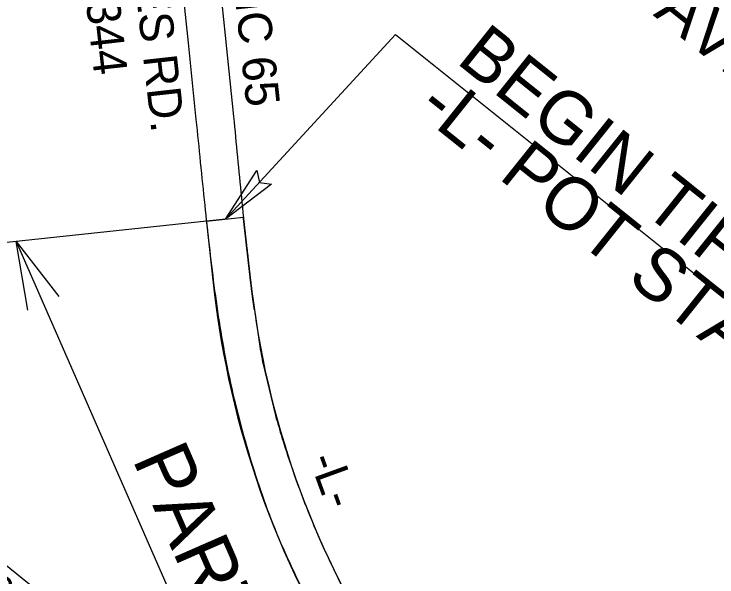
# Model space of a CAD drawing. Extents: x 1730256 to 1738218, y 910410 to 917906.
# Drawn here: x 1735145.7 to 1735520.4, y 915705.2 to 916005.2 of the extents above; entities that cross this region are included whole.
import ezdxf

# ---------------------------------------------------------------- set-up
doc = ezdxf.new("R2010")
doc.units = 0
for name, color, linetype in [('Old_Level_23', 7, 'Continuous'), ('Old_Level_3', 7, 'Continuous'), ('Prop DSN Text', 7, 'Continuous'), ('Prop EOT', 7, 'Continuous'), ('Prop Horizontal Alignment Direction Label', 7, 'Continuous'), ('Prop Shade Light', 7, 'Continuous'), ('Sheet Data Field CELL', 7, 'Continuous')]:
    doc.layers.add(name, color=color, linetype=linetype)

msp = doc.modelspace()

# ---------------------------------------------------------------- linework, layer by layer
at = {"layer": 'Old_Level_23'}
for p, q in [((1735258.41, 915895.78), (1735097.13, 915878.75)), ((1735146.86, 915884), (1735391.91, 915324.39))]:
    msp.add_line(p, q, dxfattribs=at)
at = {"layer": 'Old_Level_3'}
for p, q in [((1735272.09, 915859.75), (1735276.11, 915831.82)), ((1735278.29, 915819.37), (1735285.1, 915791.17))]:
    msp.add_line(p, q, dxfattribs=at)
for points in [[(1735247.81, 916093.77), (1735249.46, 916078.82), (1735253.85, 916036.52), (1735258.32, 915993.7), (1735262.74, 915950.51)], [(1735227.91, 916091.68), (1735229.71, 916074.46), (1735234.16, 916032), (1735238.59, 915989.91), (1735242.69, 915948.94)]]:
    msp.add_lwpolyline(points, dxfattribs=at)
for points in [[(1735262.74, 915950.51), (1735266.87, 915907.53), (1735271.65, 915863.46), (1735272.09, 915859.75)], [(1735242.69, 915948.94), (1735247.35, 915903.38), (1735252.28, 915860.46), (1735259.33, 915816.86), (1735270.45, 915772.23), (1735284.64, 915731.05), (1735303.25, 915691.23), (1735326.98, 915650.38), (1735351.32, 915614.71)], [(1735276.11, 915831.82), (1735277.9, 915821.51), (1735278.29, 915819.37)], [(1735285.1, 915791.17), (1735288.52, 915779.54), (1735302.56, 915739.9), (1735320.07, 915701.16), (1735342.82, 915660.37), (1735365.49, 915624.75)]]:
    msp.add_spline(points, degree=3, dxfattribs=at)
at = {"layer": 'Prop DSN Text'}
for p, q in [((1735258.41, 915895.78), (1735349.06, 915994.36)), ((1735349.06, 915994.36), (1735699.95, 915713.54)), ((1734996.62, 915827.33), (1735214.11, 915653.28))]:
    msp.add_line(p, q, dxfattribs=at)
msp.add_lwpolyline([(1735282.92, 915914.55), (1735258.41, 915895.78), (1735275.07, 915921.78), (1735276.47, 915915.42)], close=True, dxfattribs=at)
msp.add_lwpolyline([(1735153.04, 915847.42), (1735146.86, 915884), (1735169.53, 915854.63)], dxfattribs=at)
at = {"layer": 'Prop EOT'}
msp.add_line((1735267.95, 915896.78), (1735248.26, 915894.71), dxfattribs=at)
for radius in [485, 465]:
    msp.add_arc((1735734.25, 915912.74), radius, 188.0669, 214.0997, dxfattribs=at)
for points in [[(1735248.26, 915894.71), (1735248.34, 915894.03), (1735248.41, 915893.36), (1735248.48, 915892.69), (1735248.56, 915892.02), (1735248.63, 915891.35), (1735248.7, 915890.68), (1735248.78, 915890), (1735248.85, 915889.33), (1735248.93, 915888.66), (1735249, 915887.99), (1735249.07, 915887.32), (1735249.15, 915886.65), (1735249.22, 915885.97), (1735249.29, 915885.3), (1735249.37, 915884.63), (1735249.44, 915883.96), (1735249.51, 915883.29), (1735249.59, 915882.62), (1735249.66, 915881.94), (1735249.74, 915881.27), (1735249.81, 915880.6), (1735249.88, 915879.93), (1735249.96, 915879.26), (1735250.03, 915878.59), (1735250.1, 915877.91), (1735250.18, 915877.24), (1735250.25, 915876.57), (1735250.32, 915875.9), (1735250.4, 915875.23), (1735250.47, 915874.56), (1735250.54, 915873.88), (1735250.62, 915873.21), (1735250.69, 915872.54), (1735250.77, 915871.87), (1735250.84, 915871.2), (1735250.91, 915870.53), (1735250.99, 915869.85), (1735251.06, 915869.18), (1735251.13, 915868.51), (1735251.21, 915867.84), (1735251.28, 915867.17), (1735251.35, 915866.5), (1735251.43, 915865.82), (1735251.5, 915865.15), (1735251.58, 915864.48), (1735251.65, 915863.81), (1735251.72, 915863.14), (1735251.8, 915862.47), (1735251.87, 915861.79), (1735251.95, 915861.11), (1735252.02, 915860.42), (1735252.1, 915859.74), (1735252.18, 915859.05), (1735252.26, 915858.37), (1735252.34, 915857.68), (1735252.42, 915856.99), (1735252.5, 915856.31), (1735252.59, 915855.62), (1735252.67, 915854.94), (1735252.76, 915854.26), (1735252.84, 915853.57), (1735252.93, 915852.89), (1735253.02, 915852.2), (1735253.11, 915851.52), (1735253.2, 915850.83), (1735253.29, 915850.15), (1735253.38, 915849.47), (1735253.47, 915848.78), (1735253.57, 915848.1), (1735253.66, 915847.42), (1735253.76, 915846.73), (1735253.86, 915846.05), (1735254.05, 915844.68)], [(1735267.95, 915896.78), (1735268.02, 915896.11), (1735268.1, 915895.44), (1735268.17, 915894.77), (1735268.25, 915894.1), (1735268.33, 915893.43), (1735268.4, 915892.75), (1735268.48, 915892.08), (1735268.56, 915891.41), (1735268.63, 915890.74), (1735268.71, 915890.07), (1735268.79, 915889.4), (1735268.86, 915888.73), (1735268.94, 915888.06), (1735269.01, 915887.38), (1735269.09, 915886.71), (1735269.17, 915886.04), (1735269.24, 915885.37), (1735269.32, 915884.7), (1735269.4, 915884.03), (1735269.47, 915883.36), (1735269.55, 915882.68), (1735269.63, 915882.01), (1735269.7, 915881.34), (1735269.78, 915880.67), (1735269.86, 915880), (1735269.93, 915879.33), (1735270.01, 915878.66), (1735270.08, 915877.98), (1735270.16, 915877.31), (1735270.24, 915876.64), (1735270.31, 915875.97), (1735270.39, 915875.3), (1735270.47, 915874.63), (1735270.54, 915873.96), (1735270.62, 915873.29), (1735270.7, 915872.61), (1735270.77, 915871.94), (1735270.85, 915871.27), (1735270.93, 915870.6), (1735271, 915869.93), (1735271.08, 915869.26), (1735271.15, 915868.59), (1735271.23, 915867.91), (1735271.31, 915867.24), (1735271.38, 915866.57), (1735271.46, 915865.9), (1735271.54, 915865.23), (1735271.61, 915864.56), (1735271.69, 915863.89), (1735271.76, 915863.23), (1735271.84, 915862.57), (1735271.92, 915861.91), (1735272, 915861.26), (1735272.08, 915860.6), (1735272.16, 915859.94), (1735272.24, 915859.29), (1735272.32, 915858.63), (1735272.4, 915857.97), (1735272.49, 915857.32), (1735272.57, 915856.66), (1735272.66, 915856.01), (1735272.74, 915855.35), (1735272.83, 915854.69), (1735272.92, 915854.04), (1735273.01, 915853.38), (1735273.1, 915852.73), (1735273.19, 915852.07), (1735273.28, 915851.42), (1735273.38, 915850.76), (1735273.47, 915850.11), (1735273.56, 915849.45), (1735273.66, 915848.8), (1735273.86, 915847.49)]]:
    msp.add_spline(points, degree=3, dxfattribs=at)
at = {"layer": 'Prop Shade Light'}
msp.add_line((1735267.95, 915896.78), (1735248.26, 915894.71), dxfattribs=at)
for radius in [485, 465]:
    msp.add_arc((1735734.25, 915912.74), radius, 188.0669, 214.0997, dxfattribs=at)
for points in [[(1735248.26, 915894.71), (1735248.29, 915894.48), (1735248.31, 915894.26), (1735248.34, 915894.03), (1735248.36, 915893.81), (1735248.39, 915893.59), (1735248.41, 915893.36), (1735248.43, 915893.14), (1735248.46, 915892.91), (1735248.48, 915892.69), (1735248.51, 915892.47), (1735248.53, 915892.24), (1735248.56, 915892.02), (1735248.58, 915891.79), (1735248.61, 915891.57), (1735248.63, 915891.35), (1735248.66, 915891.12), (1735248.68, 915890.9), (1735248.7, 915890.68), (1735248.73, 915890.45), (1735248.75, 915890.23), (1735248.78, 915890), (1735248.8, 915889.78), (1735248.83, 915889.56), (1735248.85, 915889.33), (1735248.88, 915889.11), (1735248.9, 915888.88), (1735248.93, 915888.66), (1735248.95, 915888.44), (1735248.97, 915888.21), (1735249, 915887.99), (1735249.02, 915887.76), (1735249.05, 915887.54), (1735249.07, 915887.32), (1735249.1, 915887.09), (1735249.12, 915886.87), (1735249.15, 915886.65), (1735249.17, 915886.42), (1735249.2, 915886.2), (1735249.22, 915885.97), (1735249.24, 915885.75), (1735249.27, 915885.53), (1735249.29, 915885.3), (1735249.32, 915885.08), (1735249.34, 915884.85), (1735249.37, 915884.63), (1735249.39, 915884.41), (1735249.42, 915884.18), (1735249.44, 915883.96), (1735249.47, 915883.73), (1735249.49, 915883.51), (1735249.51, 915883.29), (1735249.54, 915883.06), (1735249.56, 915882.84), (1735249.59, 915882.62), (1735249.61, 915882.39), (1735249.64, 915882.17), (1735249.66, 915881.94), (1735249.69, 915881.72), (1735249.71, 915881.5), (1735249.74, 915881.27), (1735249.76, 915881.05), (1735249.78, 915880.82), (1735249.81, 915880.6), (1735249.83, 915880.38), (1735249.86, 915880.15), (1735249.88, 915879.93), (1735249.91, 915879.7), (1735249.93, 915879.48), (1735249.96, 915879.26), (1735249.98, 915879.03), (1735250.01, 915878.81), (1735250.03, 915878.59), (1735250.05, 915878.4), (1735250.07, 915878.21), (1735250.09, 915878.02)], [(1735269.82, 915880.34), (1735269.8, 915880.45), (1735269.79, 915880.56), (1735269.78, 915880.67), (1735269.75, 915880.89), (1735269.73, 915881.12), (1735269.7, 915881.34), (1735269.68, 915881.57), (1735269.65, 915881.79), (1735269.63, 915882.01), (1735269.6, 915882.24), (1735269.58, 915882.46), (1735269.55, 915882.68), (1735269.52, 915882.91), (1735269.5, 915883.13), (1735269.47, 915883.36), (1735269.45, 915883.58), (1735269.42, 915883.8), (1735269.4, 915884.03), (1735269.37, 915884.25), (1735269.35, 915884.47), (1735269.32, 915884.7), (1735269.3, 915884.92), (1735269.27, 915885.15), (1735269.24, 915885.37), (1735269.22, 915885.59), (1735269.19, 915885.82), (1735269.17, 915886.04), (1735269.14, 915886.26), (1735269.12, 915886.49), (1735269.09, 915886.71), (1735269.07, 915886.94), (1735269.04, 915887.16), (1735269.01, 915887.38), (1735268.99, 915887.61), (1735268.96, 915887.83), (1735268.94, 915888.06), (1735268.91, 915888.28), (1735268.89, 915888.5), (1735268.86, 915888.73), (1735268.84, 915888.95), (1735268.81, 915889.17), (1735268.79, 915889.4), (1735268.76, 915889.62), (1735268.73, 915889.85), (1735268.71, 915890.07), (1735268.68, 915890.29), (1735268.66, 915890.52), (1735268.63, 915890.74), (1735268.61, 915890.96), (1735268.58, 915891.19), (1735268.56, 915891.41), (1735268.53, 915891.64), (1735268.51, 915891.86), (1735268.48, 915892.08), (1735268.45, 915892.31), (1735268.43, 915892.53), (1735268.4, 915892.75), (1735268.38, 915892.98), (1735268.35, 915893.2), (1735268.33, 915893.43), (1735268.3, 915893.65), (1735268.28, 915893.87), (1735268.25, 915894.1), (1735268.23, 915894.32), (1735268.2, 915894.54), (1735268.17, 915894.77), (1735268.15, 915894.99), (1735268.12, 915895.22), (1735268.1, 915895.44), (1735268.07, 915895.66), (1735268.05, 915895.89), (1735268.02, 915896.11), (1735268, 915896.34), (1735267.97, 915896.56), (1735267.95, 915896.78)], [(1735271.69, 915863.9), (1735271.66, 915864.12), (1735271.64, 915864.34), (1735271.61, 915864.56), (1735271.59, 915864.78), (1735271.56, 915865), (1735271.54, 915865.23), (1735271.51, 915865.45), (1735271.49, 915865.68), (1735271.46, 915865.9), (1735271.43, 915866.12), (1735271.41, 915866.35), (1735271.38, 915866.57), (1735271.36, 915866.8), (1735271.33, 915867.02), (1735271.31, 915867.24), (1735271.28, 915867.47), (1735271.26, 915867.69), (1735271.23, 915867.91), (1735271.21, 915868.14), (1735271.18, 915868.36), (1735271.15, 915868.59), (1735271.13, 915868.81), (1735271.1, 915869.03), (1735271.08, 915869.26), (1735271.05, 915869.48), (1735271.03, 915869.7), (1735271, 915869.93), (1735270.98, 915870.15), (1735270.95, 915870.38), (1735270.93, 915870.6), (1735270.9, 915870.82), (1735270.87, 915871.05), (1735270.85, 915871.27), (1735270.82, 915871.49), (1735270.8, 915871.72), (1735270.77, 915871.94), (1735270.75, 915872.17), (1735270.72, 915872.39), (1735270.7, 915872.61), (1735270.67, 915872.84), (1735270.64, 915873.06), (1735270.62, 915873.29), (1735270.59, 915873.51), (1735270.57, 915873.73), (1735270.54, 915873.96), (1735270.52, 915874.18), (1735270.49, 915874.4), (1735270.47, 915874.63), (1735270.44, 915874.85), (1735270.42, 915875.08), (1735270.39, 915875.3), (1735270.36, 915875.52), (1735270.34, 915875.75), (1735270.31, 915875.97), (1735270.29, 915876.19), (1735270.26, 915876.42), (1735270.24, 915876.64), (1735270.21, 915876.87), (1735270.19, 915877.09), (1735270.16, 915877.31), (1735270.14, 915877.54), (1735270.11, 915877.76), (1735270.08, 915877.98), (1735270.06, 915878.21), (1735270.03, 915878.43), (1735270.01, 915878.66), (1735269.98, 915878.88), (1735269.96, 915879.1), (1735269.93, 915879.33), (1735269.91, 915879.55), (1735269.88, 915879.77), (1735269.86, 915880), (1735269.84, 915880.11), (1735269.83, 915880.23), (1735269.82, 915880.34)], [(1735250.09, 915878.02), (1735250.1, 915877.98), (1735250.1, 915877.95), (1735250.1, 915877.91), (1735250.13, 915877.69), (1735250.15, 915877.47), (1735250.18, 915877.24), (1735250.2, 915877.02), (1735250.23, 915876.79), (1735250.25, 915876.57), (1735250.28, 915876.35), (1735250.3, 915876.12), (1735250.32, 915875.9), (1735250.35, 915875.68), (1735250.37, 915875.45), (1735250.4, 915875.23), (1735250.42, 915875), (1735250.45, 915874.78), (1735250.47, 915874.56), (1735250.5, 915874.33), (1735250.52, 915874.11), (1735250.54, 915873.88), (1735250.57, 915873.66), (1735250.59, 915873.44), (1735250.62, 915873.21), (1735250.64, 915872.99), (1735250.67, 915872.76), (1735250.69, 915872.54), (1735250.72, 915872.32), (1735250.74, 915872.09), (1735250.77, 915871.87), (1735250.79, 915871.65), (1735250.81, 915871.42), (1735250.84, 915871.2), (1735250.86, 915870.97), (1735250.89, 915870.75), (1735250.91, 915870.53), (1735250.94, 915870.3), (1735250.96, 915870.08), (1735250.99, 915869.85), (1735251.01, 915869.63), (1735251.04, 915869.41), (1735251.06, 915869.18), (1735251.08, 915868.96), (1735251.11, 915868.73), (1735251.13, 915868.51), (1735251.16, 915868.29), (1735251.18, 915868.06), (1735251.21, 915867.84), (1735251.23, 915867.62), (1735251.26, 915867.39), (1735251.28, 915867.17), (1735251.31, 915866.94), (1735251.33, 915866.72), (1735251.35, 915866.5), (1735251.38, 915866.27), (1735251.4, 915866.05), (1735251.43, 915865.82), (1735251.45, 915865.6), (1735251.48, 915865.38), (1735251.5, 915865.15), (1735251.53, 915864.93), (1735251.55, 915864.7), (1735251.58, 915864.48), (1735251.6, 915864.26), (1735251.62, 915864.03), (1735251.65, 915863.81), (1735251.67, 915863.59), (1735251.7, 915863.36), (1735251.72, 915863.14), (1735251.75, 915862.91), (1735251.77, 915862.69), (1735251.8, 915862.47), (1735251.82, 915862.24), (1735251.85, 915862.02), (1735251.87, 915861.79), (1735251.89, 915861.64), (1735251.9, 915861.49), (1735251.92, 915861.33)], [(1735273.86, 915847.49), (1735273.79, 915847.93), (1735273.73, 915848.36), (1735273.66, 915848.8), (1735273.63, 915849.02), (1735273.6, 915849.24), (1735273.56, 915849.45), (1735273.53, 915849.67), (1735273.5, 915849.89), (1735273.47, 915850.11), (1735273.44, 915850.33), (1735273.41, 915850.54), (1735273.38, 915850.76), (1735273.34, 915850.98), (1735273.31, 915851.2), (1735273.28, 915851.42), (1735273.25, 915851.64), (1735273.22, 915851.85), (1735273.19, 915852.07), (1735273.16, 915852.29), (1735273.13, 915852.51), (1735273.1, 915852.73), (1735273.07, 915852.95), (1735273.04, 915853.17), (1735273.01, 915853.38), (1735272.98, 915853.6), (1735272.95, 915853.82), (1735272.92, 915854.04), (1735272.89, 915854.26), (1735272.86, 915854.48), (1735272.83, 915854.69), (1735272.8, 915854.91), (1735272.77, 915855.13), (1735272.74, 915855.35), (1735272.71, 915855.57), (1735272.68, 915855.79), (1735272.66, 915856.01), (1735272.63, 915856.23), (1735272.6, 915856.44), (1735272.57, 915856.66), (1735272.54, 915856.88), (1735272.51, 915857.1), (1735272.49, 915857.32), (1735272.46, 915857.54), (1735272.43, 915857.76), (1735272.4, 915857.97), (1735272.37, 915858.19), (1735272.35, 915858.41), (1735272.32, 915858.63), (1735272.29, 915858.85), (1735272.26, 915859.07), (1735272.24, 915859.29), (1735272.21, 915859.51), (1735272.18, 915859.73), (1735272.16, 915859.94), (1735272.13, 915860.16), (1735272.1, 915860.38), (1735272.08, 915860.6), (1735272.05, 915860.82), (1735272.02, 915861.04), (1735272, 915861.26), (1735271.97, 915861.48), (1735271.94, 915861.7), (1735271.92, 915861.91), (1735271.89, 915862.13), (1735271.87, 915862.35), (1735271.84, 915862.57), (1735271.82, 915862.79), (1735271.79, 915863.01), (1735271.76, 915863.23), (1735271.74, 915863.45), (1735271.71, 915863.67), (1735271.69, 915863.89), (1735271.69, 915863.89), (1735271.69, 915863.89), (1735271.69, 915863.9)], [(1735251.92, 915861.33), (1735251.93, 915861.26), (1735251.94, 915861.18), (1735251.95, 915861.11), (1735251.97, 915860.88), (1735252, 915860.65), (1735252.02, 915860.42), (1735252.05, 915860.19), (1735252.07, 915859.96), (1735252.1, 915859.74), (1735252.13, 915859.51), (1735252.15, 915859.28), (1735252.18, 915859.05), (1735252.2, 915858.82), (1735252.23, 915858.59), (1735252.26, 915858.37), (1735252.28, 915858.14), (1735252.31, 915857.91), (1735252.34, 915857.68), (1735252.37, 915857.45), (1735252.39, 915857.22), (1735252.42, 915856.99), (1735252.45, 915856.77), (1735252.47, 915856.54), (1735252.5, 915856.31), (1735252.53, 915856.08), (1735252.56, 915855.85), (1735252.59, 915855.62), (1735252.61, 915855.4), (1735252.64, 915855.17), (1735252.67, 915854.94), (1735252.7, 915854.71), (1735252.73, 915854.48), (1735252.76, 915854.26), (1735252.78, 915854.03), (1735252.81, 915853.8), (1735252.84, 915853.57), (1735252.87, 915853.34), (1735252.9, 915853.11), (1735252.93, 915852.89), (1735252.96, 915852.66), (1735252.99, 915852.43), (1735253.02, 915852.2), (1735253.05, 915851.97), (1735253.08, 915851.75), (1735253.11, 915851.52), (1735253.14, 915851.29), (1735253.17, 915851.06), (1735253.2, 915850.83), (1735253.23, 915850.61), (1735253.26, 915850.38), (1735253.29, 915850.15), (1735253.32, 915849.92), (1735253.35, 915849.69), (1735253.38, 915849.47), (1735253.41, 915849.24), (1735253.44, 915849.01), (1735253.47, 915848.78), (1735253.5, 915848.55), (1735253.54, 915848.33), (1735253.57, 915848.1), (1735253.6, 915847.87), (1735253.63, 915847.64), (1735253.66, 915847.42), (1735253.69, 915847.19), (1735253.73, 915846.96), (1735253.76, 915846.73), (1735253.79, 915846.51), (1735253.82, 915846.28), (1735253.86, 915846.05), (1735253.92, 915845.59), (1735253.99, 915845.14), (1735254.05, 915844.68)]]:
    msp.add_open_spline(points, degree=3, dxfattribs=at)

# ---------------------------------------------------------------- texts
at = {"layer": 'Old_Level_23'}
msp.add_text('PART I            B-4864', height=30, rotation=293.6484, dxfattribs=at).set_placement((1735208.57, 915768.01))
at = {"layer": 'Prop DSN Text'}
for s, height, rotation, p in [('HAYNES RD.', 18, 276.3812, (1735202.7, 916087.69)), ('SR 2344', 18, 276.3812, (1735178.05, 916065.18)), ('TO NC 65', 18, 276.0686, (1735258.26, 916062.86)), ('BEGIN TIP PROJECT B-4864', 28, 321.3297, (1735380.83, 915979.55)), ('-L- POT STA. 13+00.00', 28, 321.3297, (1735359.59, 915953.01)), ('-L- POT STA. 16+00.33', 15.75, 321.3297, (1734987.12, 915809))]:
    msp.add_text(s, height=height, rotation=rotation, dxfattribs=at).set_placement(p)
at = {"layer": 'Prop Horizontal Alignment Direction Label'}
msp.add_text('-L-', height=18, rotation=289.9505, dxfattribs=at).set_placement((1735302.81, 915767.91))
at = {"layer": 'Sheet Data Field CELL'}
for s, p in [('BRIDGE NO. 13 OVER TROUBLESOME CREEK ON SR 2344', (1735157.2, 916390.24)), ('BRIDGE NO. 12 OVER TROUBLESOME CREEK ON SR 2343', (1735130.01, 916356.27)), ('GRADING, DRAINAGE, PAVING AND CULVERTS', (1735181.48, 916248.42))]:
    msp.add_text(s, height=25.0002, rotation=321.3297, dxfattribs=at).set_placement(p)

doc.saveas('drawing.dxf')
